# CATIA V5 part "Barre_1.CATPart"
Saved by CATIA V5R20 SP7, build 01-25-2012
Part number: Barre_1
Bounding box of the stored display mesh (mm): x -2 to 0, y 24.773 to 32.173, z 9.42 to 11.42
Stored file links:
  J:\IFMA\IAO\système avant mef\Barre_1.CATPart
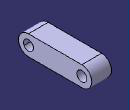
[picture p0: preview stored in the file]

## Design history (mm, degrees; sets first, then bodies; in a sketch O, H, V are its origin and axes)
Body1 (main body)
  Plane1: stored without definition
  Point1 "Point.E": stored without definition
  Point2 "Point.A": stored without definition
  Point3 "Point.A": stored without definition
  Line1 "barre_1": stored without definition
  Sketch1 on Plane1, origin (-2, 0, 0), H (0, 1, 0), V (0, 0, 1)
    point P1 (31.1733, 10.4199)
    point P2 (25.7733, 10.4199)
    line L1 (31.1733, 9.4199) -> (25.7733, 9.4199)
    line L2 (25.7733, 11.4199) -> (31.1733, 11.4199)
    arc A1 centre (25.7733, 10.4199) radius 1 from (25.7733, 9.4199) to (25.7733, 11.4199) cw
    arc A2 centre (31.1733, 10.4199) radius 1 from (31.1733, 11.4199) to (31.1733, 9.4199) cw
    reference projected point E1 (25.7733, 10.4199) from Point1
    reference projected point E2 (31.1733, 10.4199) from Point3
    reference projected line E3 (25.7733, 10.4199) -> (31.1733, 10.4199) from Line1
    distance L2 E3 = 1 {= 2mm/2}
    tangency: A1 L1, A2 L1, A1 L2, A2 L2
    coincidence: P2 E1, P1 E2
  Pad1: profile Sketch1, direction (1, 0, 0), length 2 {= 2mm}
  Sketch2 on end face of Pad1, origin (0, 28.6056, 10.7749), H (0, 1, 0), V (0, 0, 1)
    point P1 (2.5677, -0.355)
    reference projected point E1 (2.5677, -0.355) from Point4
    coincidence: P1 E1
  Hole1: placed by Sketch2, at (0, 31.1733, 10.4199) direction (-1, 0, 0), diameter 1 {= 2mm/2}, through (limit type 3)
  Sketch3 on start face of Pad1, origin (-2, 26.3859, 10.8215), H (0, 1, 0), V (0, 0, -1)
    point P1 (-0.6125, 0.4015)
    reference projected point E1 (-0.6125, 0.4015) from Point5
    coincidence: P1 E1
  Hole2: placed by Sketch3, at (-2, 25.7733, 10.4199) direction (1, 0, 0), diameter 1 {= 2mm/2}, through (limit type 3)
  Point4 "Point.A": stored without definition
  Point5 "Point.E": stored without definition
